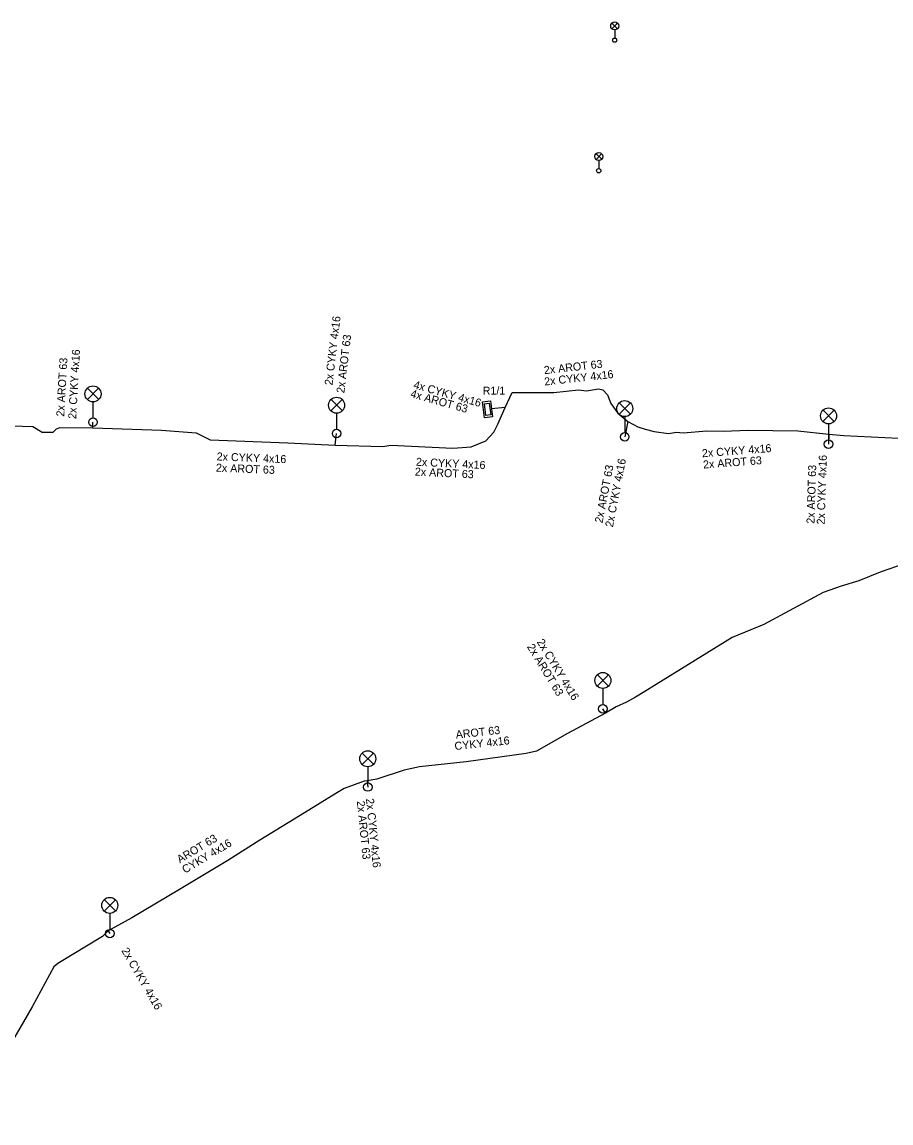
# Model space of a CAD drawing. Extents: x -641884 to -641258, y -1196509 to -1195931.
# Drawn here: x -641795 to -641713.6, y -1196103.1 to -1195999.9 of the extents above; entities that cross this region are included whole.
import ezdxf

# ---------------------------------------------------------------- set-up
doc = ezdxf.new("R2010")
doc.units = 0
for name, color, linetype in [('CIZÍ_PODZEM', 7, 'Continuous'), ('CIZÍ_PODZEM_POPIS', 7, 'Continuous'), ('TECH_OCHR_PÁSMO_HRAN', 7, 'Continuous'), ('Vrstva 22', 7, 'Continuous'), ('Vrstva 31', 7, 'Continuous'), ('ZP_EON', 7, 'Continuous'), ('ZP_EON_POPIS', 7, 'Continuous')]:
    doc.layers.add(name, color=color, linetype=linetype)

msp = doc.modelspace()

# ---------------------------------------------------------------- linework, layer by layer
at = {"layer": 'CIZÍ_PODZEM'}
for points in [[(-641751.65, -1196036.96), (-641751.84, -1196035.47), (-641751.1, -1196035.38), (-641750.9, -1196036.86)], [(-641751.52, -1196036.74), (-641751.67, -1196035.65), (-641751.22, -1196035.59), (-641751.08, -1196036.68)]]:
    msp.add_lwpolyline(points, close=True, dxfattribs=at)
at = {"layer": 'TECH_OCHR_PÁSMO_HRAN'}
for p, q in [((-641749.72, -1196036), (-641751, -1196036.12)), ((-641788.38, -1196037.9), (-641788.35, -1196037.37)), ((-641738.24, -1196037.3), (-641738.52, -1196038.75)), ((-641765.65, -1196039.53), (-641765.52, -1196038.43)), ((-641719.39, -1196038.48), (-641719.42, -1196039.43)), ((-641740.32, -1196064.64), (-641740.57, -1196064.23)), ((-641762.66, -1196070.98), (-641762.6, -1196071.57))]:
    msp.add_line(p, q, dxfattribs=at)
for points in [[(-641749.72, -1196036), (-641749.06, -1196034.58), (-641745.17, -1196034.6), (-641742.84, -1196034.34), (-641742.09, -1196034.44), (-641740.99, -1196034.24), (-641740.58, -1196034.35), (-641740.13, -1196034.8), (-641739.83, -1196035.61), (-641739.17, -1196036.52), (-641738.24, -1196037.3)], [(-641765.65, -1196039.53), (-641761.19, -1196039.64), (-641760.43, -1196039.53), (-641754.63, -1196039.81), (-641752.92, -1196039.67), (-641751.54, -1196039.11), (-641750.79, -1196038.31), (-641750.41, -1196037.56), (-641749.72, -1196036)], [(-641813.45, -1196037.19), (-641813.08, -1196037.37), (-641811.77, -1196037.5), (-641810.48, -1196037.54), (-641807.46, -1196037.55), (-641804.59, -1196037.85), (-641801.71, -1196038.05), (-641796.66, -1196037.81), (-641795.99, -1196037.7), (-641793.99, -1196037.76), (-641793.1, -1196038.32), (-641792.08, -1196038.29), (-641791.76, -1196038), (-641791.46, -1196037.86), (-641788.38, -1196037.9)], [(-641738.24, -1196037.3), (-641737.29, -1196037.8), (-641736.6, -1196038.03), (-641735.75, -1196038.23), (-641734.41, -1196038.43), (-641733.66, -1196038.29), (-641733.04, -1196038.36), (-641730.81, -1196038.19), (-641729.27, -1196038.21), (-641726.98, -1196038.11), (-641722.29, -1196038.18), (-641719.39, -1196038.48)], [(-641788.38, -1196037.9), (-641781.93, -1196038.12), (-641780.3, -1196038.23), (-641778.67, -1196038.38), (-641777.37, -1196039.02), (-641770.1, -1196039.31), (-641765.65, -1196039.53)], [(-641719.39, -1196038.48), (-641717.98, -1196038.63), (-641711.58, -1196038.92), (-641704.47, -1196039.22), (-641703.2, -1196039.32), (-641701.33, -1196039.49), (-641699.59, -1196039.56), (-641695.1, -1196039.67), (-641690.64, -1196039.81)], [(-641647.27, -1196049.94), (-641647.5, -1196049.92), (-641654.02, -1196049.51), (-641660.8, -1196049.42), (-641661.95, -1196049.35), (-641670.08, -1196049.16), (-641688.67, -1196048.56), (-641704.99, -1196048.06), (-641705.44, -1196048.15), (-641709.91, -1196049.79), (-641714.57, -1196051.44), (-641716.59, -1196052.24), (-641718.25, -1196052.73), (-641719.93, -1196053.33), (-641725.48, -1196056.34), (-641728.46, -1196057.54), (-641736.62, -1196062.62), (-641737.5, -1196063.15), (-641738.36, -1196063.61), (-641739.31, -1196064.06), (-641740.32, -1196064.64)], [(-641740.32, -1196064.64), (-641743.88, -1196066.56), (-641746.79, -1196068.2), (-641747.74, -1196068.44), (-641753.37, -1196069.21), (-641757.74, -1196069.68), (-641759.18, -1196069.98), (-641761.75, -1196070.82), (-641762.66, -1196070.98)], [(-641762.66, -1196070.98), (-641762.93, -1196071.03), (-641764.8, -1196071.72), (-641765.6, -1196072.17), (-641768.53, -1196074), (-641772.73, -1196076.56), (-641775.71, -1196078.45), (-641780.24, -1196081.17), (-641784.7, -1196083.82), (-641786.93, -1196085.05)], [(-641786.93, -1196085.05), (-641787.47, -1196085.58), (-641791.63, -1196088.11), (-641792.01, -1196088.41), (-641794.06, -1196092.16), (-641796.03, -1196095.59), (-641799.51, -1196100.97), (-641800.31, -1196102.27), (-641800.71, -1196102.36), (-641804.66, -1196102.18), (-641805.32, -1196102.32), (-641805.26, -1196103.06)]]:
    msp.add_lwpolyline(points, dxfattribs=at)
at = {"layer": 'Vrstva 31'}
for p, q in [((-641739.72, -1196000.5), (-641739.2, -1195999.97)), ((-641739.19, -1196000.49), (-641739.72, -1195999.97)), ((-641739.46, -1196000.61), (-641739.46, -1196001.36)), ((-641741.21, -1196012.74), (-641740.69, -1196012.21)), ((-641740.68, -1196012.73), (-641741.21, -1196012.21)), ((-641740.95, -1196012.85), (-641740.95, -1196013.6)), ((-641788.88, -1196035.25), (-641787.82, -1196034.19)), ((-641787.81, -1196035.24), (-641788.86, -1196034.18)), ((-641788.35, -1196035.47), (-641788.35, -1196036.97)), ((-641766.05, -1196036.31), (-641764.99, -1196035.25)), ((-641764.98, -1196036.3), (-641766.03, -1196035.24)), ((-641765.52, -1196036.53), (-641765.52, -1196038.03)), ((-641739.05, -1196036.63), (-641737.99, -1196035.57)), ((-641737.98, -1196036.62), (-641739.03, -1196035.56)), ((-641719.95, -1196037.31), (-641718.89, -1196036.25)), ((-641718.88, -1196037.3), (-641719.93, -1196036.24)), ((-641738.52, -1196036.85), (-641738.52, -1196038.35)), ((-641719.42, -1196037.53), (-641719.42, -1196039.03)), ((-641741.1, -1196062.11), (-641740.04, -1196061.05)), ((-641740.03, -1196062.1), (-641741.08, -1196061.04)), ((-641740.57, -1196062.33), (-641740.57, -1196063.83)), ((-641763.13, -1196069.45), (-641762.07, -1196068.39)), ((-641762.06, -1196069.44), (-641763.11, -1196068.38)), ((-641762.6, -1196069.67), (-641762.6, -1196071.17)), ((-641787.31, -1196083.19), (-641786.25, -1196082.13)), ((-641786.24, -1196083.18), (-641787.29, -1196082.12)), ((-641786.78, -1196083.41), (-641786.78, -1196084.91))]:
    msp.add_line(p, q, dxfattribs=at)
for centre, radius in [((-641739.46, -1196000.23), 0.375), ((-641739.46, -1196001.56), 0.2), ((-641740.95, -1196012.47), 0.375), ((-641740.95, -1196013.8), 0.2), ((-641788.35, -1196034.72), 0.75), ((-641765.52, -1196035.78), 0.75), ((-641738.52, -1196036.1), 0.75), ((-641719.42, -1196036.78), 0.75), ((-641788.35, -1196037.37), 0.4), ((-641765.52, -1196038.43), 0.4), ((-641738.52, -1196038.75), 0.4), ((-641719.42, -1196039.43), 0.4), ((-641740.57, -1196061.58), 0.75), ((-641740.57, -1196064.23), 0.4), ((-641762.6, -1196068.92), 0.75), ((-641762.6, -1196071.57), 0.4), ((-641786.78, -1196082.66), 0.75), ((-641786.78, -1196085.31), 0.4)]:
    msp.add_circle(centre, radius, dxfattribs=at)
at = {"layer": 'ZP_EON'}
for p, q in [((-641749.72, -1196036), (-641751, -1196036.12)), ((-641788.38, -1196037.9), (-641788.35, -1196037.37)), ((-641738.24, -1196037.3), (-641738.52, -1196038.75)), ((-641765.65, -1196039.53), (-641765.52, -1196038.43)), ((-641719.39, -1196038.48), (-641719.42, -1196039.43)), ((-641740.32, -1196064.64), (-641740.57, -1196064.23)), ((-641762.66, -1196070.98), (-641762.6, -1196071.57)), ((-641786.93, -1196085.05), (-641786.78, -1196085.31))]:
    msp.add_line(p, q, dxfattribs=at)
for points in [[(-641749.72, -1196036), (-641749.06, -1196034.58), (-641745.17, -1196034.6), (-641742.84, -1196034.34), (-641742.09, -1196034.44), (-641740.99, -1196034.24), (-641740.58, -1196034.35), (-641740.13, -1196034.8), (-641739.83, -1196035.61), (-641739.17, -1196036.52), (-641738.24, -1196037.3)], [(-641765.65, -1196039.53), (-641761.19, -1196039.64), (-641760.43, -1196039.53), (-641754.63, -1196039.81), (-641752.92, -1196039.67), (-641751.54, -1196039.11), (-641750.79, -1196038.31), (-641750.41, -1196037.56), (-641749.72, -1196036)], [(-641813.45, -1196037.19), (-641813.08, -1196037.37), (-641811.77, -1196037.5), (-641810.48, -1196037.54), (-641807.46, -1196037.55), (-641804.59, -1196037.85), (-641801.71, -1196038.05), (-641796.66, -1196037.81), (-641795.99, -1196037.7), (-641793.99, -1196037.76), (-641793.1, -1196038.32), (-641792.08, -1196038.29), (-641791.76, -1196038), (-641791.46, -1196037.86), (-641788.38, -1196037.9)], [(-641738.24, -1196037.3), (-641737.29, -1196037.8), (-641736.6, -1196038.03), (-641735.75, -1196038.23), (-641734.41, -1196038.43), (-641733.66, -1196038.29), (-641733.04, -1196038.36), (-641730.81, -1196038.19), (-641729.27, -1196038.21), (-641726.98, -1196038.11), (-641722.29, -1196038.18), (-641719.39, -1196038.48)], [(-641788.38, -1196037.9), (-641781.93, -1196038.12), (-641780.3, -1196038.23), (-641778.67, -1196038.38), (-641777.37, -1196039.02), (-641770.1, -1196039.31), (-641765.65, -1196039.53)], [(-641719.39, -1196038.48), (-641717.98, -1196038.63), (-641711.58, -1196038.92), (-641704.47, -1196039.22), (-641703.2, -1196039.32), (-641701.33, -1196039.49), (-641699.59, -1196039.56), (-641695.1, -1196039.67), (-641690.64, -1196039.81)], [(-641647.27, -1196049.94), (-641647.5, -1196049.92), (-641654.02, -1196049.51), (-641660.8, -1196049.42), (-641661.95, -1196049.35), (-641670.08, -1196049.16), (-641688.67, -1196048.56), (-641704.99, -1196048.06), (-641705.44, -1196048.15), (-641709.91, -1196049.79), (-641714.57, -1196051.44), (-641716.59, -1196052.24), (-641718.25, -1196052.73), (-641719.93, -1196053.33), (-641725.48, -1196056.34), (-641728.46, -1196057.54), (-641736.62, -1196062.62), (-641737.5, -1196063.15), (-641738.36, -1196063.61), (-641739.31, -1196064.06), (-641740.32, -1196064.64)], [(-641740.32, -1196064.64), (-641743.88, -1196066.56), (-641746.79, -1196068.2), (-641747.74, -1196068.44), (-641753.37, -1196069.21), (-641757.74, -1196069.68), (-641759.18, -1196069.98), (-641761.75, -1196070.82), (-641762.66, -1196070.98)], [(-641762.66, -1196070.98), (-641762.93, -1196071.03), (-641764.8, -1196071.72), (-641765.6, -1196072.17), (-641768.53, -1196074), (-641772.73, -1196076.56), (-641775.71, -1196078.45), (-641780.24, -1196081.17), (-641784.7, -1196083.82), (-641786.93, -1196085.05)], [(-641786.93, -1196085.05), (-641787.47, -1196085.58), (-641791.63, -1196088.11), (-641792.01, -1196088.41), (-641794.06, -1196092.16), (-641796.03, -1196095.59), (-641799.51, -1196100.97), (-641800.31, -1196102.27), (-641800.71, -1196102.36), (-641804.66, -1196102.18), (-641805.32, -1196102.32), (-641805.26, -1196103.06)]]:
    msp.add_lwpolyline(points, dxfattribs=at)

# ---------------------------------------------------------------- texts
at = {"layer": 'CIZÍ_PODZEM_POPIS'}
msp.add_text('R1/1', height=0.75, dxfattribs=at).set_placement((-641751.83, -1196034.79))
at = {"layer": 'Vrstva 22'}
for s, rotation, p in [('2x AROT 63', 83.2599, (-641764.8, -1196034.68)), ('2x AROT 63', 86.7603, (-641791.05, -1196036.86)), ('2x AROT 63', 6.3672, (-641746.05, -1196032.87)), ('4x AROT 63', 344.2192, (-641758.66, -1196035.01)), ('2x AROT 63', 4.3594, (-641731.15, -1196041.72)), ('2x AROT 63', 357.7157, (-641776.84, -1196042)), ('2x AROT 63', 357.2361, (-641758.2, -1196042.37)), ('2x AROT 63', 79.0705, (-641740.61, -1196046.87)), ('2x AROT 63', 88.1913, (-641720.74, -1196046.9)), ('2x AROT 63', 301.373, (-641747.71, -1196058.42)), ('AROT 63', 6.1386, (-641754.32, -1196067.03)), ('2x AROT 63', 275.8067, (-641763.63, -1196072.9)), ('AROT 63', 30.9824, (-641780.21, -1196078.74))]:
    msp.add_text(s, height=0.75, rotation=rotation, dxfattribs=at).set_placement(p)
at = {"layer": 'ZP_EON_POPIS'}
for s, rotation, p in [('2x CYKY 4x16', 83.2599, (-641765.91, -1196033.94)), ('2x CYKY 4x16', 86.7603, (-641789.93, -1196037.08)), ('2x CYKY 4x16', 6.3672, (-641746.02, -1196033.94)), ('4x CYKY 4x16', 344.2192, (-641758.37, -1196034.18)), ('2x CYKY 4x16', 4.3594, (-641731.25, -1196040.66)), ('2x CYKY 4x16', 357.7157, (-641776.77, -1196040.95)), ('2x CYKY 4x16', 357.2361, (-641758.1, -1196041.45)), ('2x CYKY 4x16', 88.1913, (-641719.78, -1196046.97)), ('2x CYKY 4x16', 79.0705, (-641739.63, -1196047.26)), ('2x CYKY 4x16', 301.373, (-641746.79, -1196057.96)), ('CYKY 4x16', 6.1386, (-641754.43, -1196068.11)), ('2x CYKY 4x16', 275.8067, (-641762.77, -1196072.67)), ('CYKY 4x16', 30.9824, (-641779.72, -1196079.7)), ('2x CYKY 4x16', 299.9816, (-641785.72, -1196086.89))]:
    msp.add_text(s, height=0.75, rotation=rotation, dxfattribs=at).set_placement(p)

doc.saveas('drawing.dxf')
